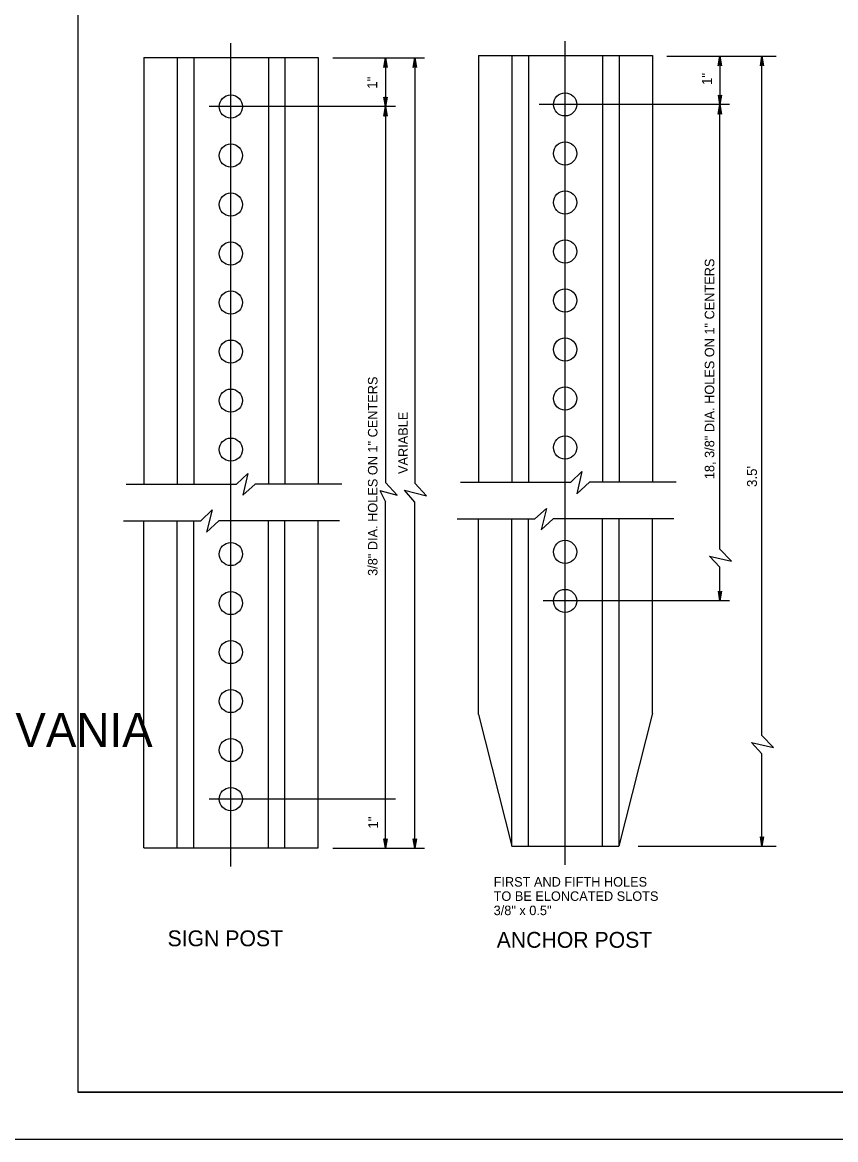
# Model space of a CAD drawing. Extents: x 644358 to 648627, y 294594 to 295782.
# Drawn here: x 647744.8 to 648001.1, y 295187.6 to 295539.8 of the extents above; entities that cross this region are included whole.
import ezdxf

# ---------------------------------------------------------------- set-up
doc = ezdxf.new("R2010")
doc.units = 0
for name, color, linetype in [('1', 7, 'Continuous'), ('2', 7, 'Continuous'), ('3', 7, 'Continuous'), ('4', 7, 'Continuous'), ('PLT-BNDY', 7, 'Continuous')]:
    doc.layers.add(name, color=color, linetype=linetype)

# ---------------------------------------------------------------- blocks, each defined once
blk = doc.blocks.new('RARROW')
at = {"layer": '3'}
blk.add_lwpolyline([(-2.2695, 0.285), (-2.184875, 0.12075), (0, 0), (-2.2695, 0.285), (-2.38575, 0.384625), (0, 0), (-2.183125, -0.108), (-2.262875, -0.2705), (0, 0), (-2.38575, -0.379125), (-2.262875, -0.2705)], dxfattribs=at)

msp = doc.modelspace()

# ---------------------------------------------------------------- linework, layer by layer
at = {"layer": '1'}
for p, q in [((647762.31, 295766.63), (647762.31, 295202.63)), ((648548.31, 295202.63), (647762.31, 295202.63)), ((647762.31, 295202.63), (648348.31, 295202.63))]:
    msp.add_line(p, q, dxfattribs=at)
at = {"layer": '2'}
for p, q in [((647783.15, 295528.71), (647838.03, 295528.71)), ((647783.15, 295528.71), (647783.15, 295394.21)), ((647793.65, 295528.71), (647793.65, 295394.21)), ((647798.9, 295528.71), (647798.9, 295394.21)), ((647822.4, 295528.71), (647822.4, 295394.21)), ((647827.53, 295528.71), (647827.53, 295394.21)), ((647838.03, 295528.71), (647838.03, 295394.21)), ((647888.53, 295529.33), (647943.4, 295529.33)), ((647888.53, 295529.33), (647888.53, 295394.83)), ((647899.03, 295529.33), (647899.03, 295394.83)), ((647904.28, 295529.33), (647904.28, 295394.83)), ((647927.65, 295529.33), (647927.65, 295394.83)), ((647932.9, 295529.33), (647932.9, 295394.83)), ((647943.4, 295529.33), (647943.4, 295394.83)), ((647812.28, 295394.21), (647815.9, 295397.58)), ((647815.9, 295397.58), (647814.28, 295390.71)), ((647917.65, 295394.83), (647921.15, 295398.21)), ((647921.15, 295398.21), (647919.53, 295391.21)), ((647777.53, 295394.21), (647812.28, 295394.21)), ((647814.28, 295390.71), (647818.15, 295394.21)), ((647845.53, 295394.21), (647818.15, 295394.21)), ((647882.9, 295394.83), (647917.65, 295394.83)), ((647919.53, 295391.21), (647923.53, 295394.83)), ((647950.9, 295394.83), (647923.53, 295394.83)), ((647801.03, 295382.71), (647804.65, 295386.08)), ((647804.65, 295386.08), (647802.9, 295379.08)), ((647906.28, 295383.33), (647910.03, 295386.58)), ((647910.03, 295386.58), (647908.28, 295379.83)), ((647776.65, 295382.71), (647801.03, 295382.71)), ((647783.15, 295279.58), (647783.15, 295382.71)), ((647793.65, 295279.58), (647793.65, 295382.71)), ((647798.9, 295279.58), (647798.9, 295382.71)), ((647802.9, 295379.08), (647806.78, 295382.71)), ((647844.78, 295382.71), (647806.78, 295382.71)), ((647822.4, 295279.58), (647822.4, 295382.71)), ((647827.53, 295279.58), (647827.53, 295382.71)), ((647838.03, 295279.58), (647838.03, 295382.71)), ((647881.9, 295383.33), (647906.28, 295383.33)), ((647888.53, 295321.58), (647888.53, 295383.33)), ((647899.03, 295280.08), (647899.03, 295383.33)), ((647904.28, 295280.08), (647904.28, 295383.33)), ((647908.28, 295379.83), (647912.15, 295383.33)), ((647950.15, 295383.33), (647912.15, 295383.33)), ((647927.65, 295280.08), (647927.65, 295383.33)), ((647932.9, 295280.08), (647932.9, 295383.33)), ((647943.4, 295322.08), (647943.4, 295383.33)), ((647888.53, 295321.58), (647899.03, 295280.08)), ((647943.4, 295322.08), (647932.78, 295280.08)), ((647783.15, 295279.58), (647838.03, 295279.58)), ((647899.03, 295280.08), (647932.78, 295280.08))]:
    msp.add_line(p, q, dxfattribs=at)
for centre in [(647810.52, 295513.24), (647915.86, 295513.91), (647915.86, 295498.46), (647810.52, 295497.79), (647810.52, 295482.34), (647915.86, 295483.01), (647810.52, 295466.9), (647915.86, 295467.56), (647810.52, 295451.45), (647915.86, 295452.11), (647810.52, 295436), (647915.86, 295436.66), (647915.86, 295421.21), (647810.52, 295420.55), (647810.52, 295405.1), (647915.86, 295405.76), (647810.52, 295372.2), (647915.86, 295372.87), (647810.52, 295356.75), (647915.86, 295357.42), (647810.52, 295341.3), (647810.52, 295325.86), (647810.52, 295310.41), (647810.52, 295294.96)]:
    msp.add_circle(centre, 3.65, dxfattribs=at)
at = {"layer": '4'}
for p, q in [((647915.9, 295274.21), (647915.9, 295533.83)), ((647810.53, 295273.71), (647810.53, 295533.21)), ((647842.65, 295528.58), (647871.53, 295528.58)), ((647859.28, 295528.58), (647859.28, 295513.21)), ((647868.53, 295528.58), (647868.53, 295394.56)), ((647947.9, 295529.08), (647982.4, 295529.08)), ((647964.65, 295529.08), (647964.65, 295513.83)), ((647977.9, 295314.96), (647977.9, 295529.08)), ((647862.4, 295513.21), (647803.65, 295513.21)), ((647859.28, 295513.21), (647859.28, 295394.78)), ((647967.65, 295513.83), (647907.65, 295513.83)), ((647964.65, 295373.78), (647964.65, 295513.83)), ((647862.9, 295390.78), (647859.28, 295394.78)), ((647872.15, 295390.56), (647868.53, 295394.56)), ((647857.51, 295392.21), (647862.9, 295390.78)), ((647857.51, 295392.21), (647859.28, 295388.61)), ((647865.28, 295392.31), (647872.15, 295390.56)), ((647868.53, 295388.56), (647865.28, 295392.31)), ((647859.28, 295279.46), (647859.28, 295388.61)), ((647868.53, 295279.46), (647868.53, 295388.56)), ((647968.28, 295369.9), (647964.65, 295373.78)), ((647961.4, 295371.53), (647968.28, 295369.9)), ((647964.65, 295368.03), (647961.4, 295371.53)), ((647964.65, 295357.46), (647964.65, 295368.03)), ((647967.65, 295357.46), (647908.9, 295357.46)), ((647977.9, 295309.21), (647974.65, 295312.83)), ((647974.65, 295312.83), (647981.53, 295311.21)), ((647981.53, 295311.21), (647977.9, 295314.96)), ((647977.9, 295280.08), (647977.9, 295309.21)), ((647862.4, 295294.96), (647803.65, 295294.96)), ((647842.65, 295279.46), (647871.53, 295279.46)), ((647938.9, 295280.08), (647982.4, 295280.08))]:
    msp.add_line(p, q, dxfattribs=at)
at = {"layer": 'PLT-BNDY'}
msp.add_lwpolyline([(647722.31, 295781.63), (648563.31, 295781.63), (648563.31, 295187.63), (647722.31, 295187.63)], close=True, dxfattribs=at)

# ---------------------------------------------------------------- block references
at = {"layer": '2', "xscale": 1.2574347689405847, "yscale": 1.3092961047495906}
for p, rotation in [((647859.28, 295528.58), 89.99999999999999), ((647868.53, 295528.58), 89.99999999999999), ((647964.65, 295529.08), 89.99999999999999), ((647977.9, 295529.08), 89.99999999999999), ((647859.28, 295513.21), -90.00000000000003), ((647964.65, 295513.83), -90.00000000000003), ((647859.28, 295513.21), 89.99999999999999), ((647964.65, 295513.83), 89.99999999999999), ((647964.65, 295357.46), -90.00000000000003), ((647859.28, 295279.46), -90.00000000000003), ((647868.53, 295279.46), -90.00000000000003), ((647977.9, 295280.08), -90.00000000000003)]:
    msp.add_blockref('RARROW', p, dxfattribs=dict(at, rotation=rotation))

# ---------------------------------------------------------------- texts
at = {"layer": '1'}
msp.add_text('COMMONWEALTH OF PENNSYLVANIA', height=10.7828, dxfattribs=at).set_placement((647519.9, 295311.36))
at = {"layer": '4'}
for s, height, p in [('1"', 3.125, (647962.13, 295520.03)), ('1"', 3.125, (647856.64, 295518.83)), ('18, 3/8" DIA. HOLES ON 1" CENTERS', 3, (647962.88, 295395.8)), (' 3/8" DIA. HOLES ON 1" CENTERS', 3, (647856.73, 295364.2)), ('VARIABLE', 3, (647866.3, 295397.43)), ("3.5'", 3.125, (647976.34, 295393.33)), ('1"', 3.125, (647856.94, 295285.66))]:
    msp.add_text(s, height=height, rotation=90, dxfattribs=at).set_placement(p)
for s, height, p in [('FIRST AND FIFTH HOLES ', 3, (647893.34, 295267.38)), ('TO BE ELONCATED SLOTS', 3, (647893.34, 295262.88)), ('3/8" x 0.5"', 3, (647893.34, 295258.38)), ('SIGN POST', 5, (647790.57, 295248.58)), ('ANCHOR POST', 5, (647894.3, 295248.1))]:
    msp.add_text(s, height=height, dxfattribs=at).set_placement(p)

doc.saveas('drawing.dxf')
